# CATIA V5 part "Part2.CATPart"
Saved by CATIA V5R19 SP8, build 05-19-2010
Part number: Points_Squelette
Bounding box of the stored display mesh (mm): x 0 to 0, y -400 to 500, z -325 to 195
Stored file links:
  G:\EU_thinkMotion\CFAO_2010\MMS_groupe1\MMS_groupe1\OK\ppiault\piault\piault_cfao\Part2.CATPart
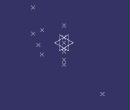
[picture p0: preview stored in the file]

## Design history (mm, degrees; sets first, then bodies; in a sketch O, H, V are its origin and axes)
Parameters
  y0 = 0 mm
  z0 = 0 mm
  y0p = -280 mm
  z0p = 0 mm
  y0s = -286 mm
  z0s = -250 mm
  y0t = 500 mm
  z0t = -300 mm
  y1 = 0 mm
  haut_axe = 195 mm
  y1p = -400 mm
  z1p = 195 mm
  y1s = 0 mm
  z1s = 62 mm
  y2 = 0 mm
  z2 = -99 mm
  y2p = 0 mm
  z2p = -64 mm
  y2s = -400 mm
  z2s = -99 mm
  y3 = 0 mm
  z3 = -190 mm
  y3p = 0 mm
  z3p = -230 mm
  y3s = -330 mm
  z3s = -190 mm
  DiametreRabatteur = 400 mm
  DiametreScie = 330 mm
  LongueurEntretoise = 130 mm
  Epaisseur = 5 mm
  bas_axe = 255 mm
  Longueur_Support = 280 mm {= DiametreRabatteur *0.7}
Set1
  Point1: (0, 0 {= y0}, 0 {= z0})
  Point2: (0, -280 {= -Longueur_Support}, 0 {= z0p})
  Point3: (0, -286 {= -0.715*DiametreRabatteur}, -275 {= -bas_axe -20mm})
  Point4: (0, 500 {= DiametreRabatteur +100mm}, -325 {= -bas_axe -70mm})
  Point5: (0, 0 {= y1}, 195 {= haut_axe})
  Point6: (0, -400 {= -DiametreRabatteur}, 195 {= haut_axe})
  Point7: (0, 0 {= y1s}, 60 {= haut_axe -Epaisseur -LongueurEntretoise})
  Point8: (0, 0 {= y2}, -100 {= -LongueurEntretoise/2 -35mm})
  Point9: (0, 0 {= y2p}, -65 {= -LongueurEntretoise /2})
  Point10: (0, -400 {= -DiametreRabatteur}, -100 {= -LongueurEntretoise/2 -35mm})
  Point11: (0, 0 {= y3}, -190 {= -bas_axe +LongueurEntretoise/2})
  Point12: (0, 0 {= y3p}, -245 {= -bas_axe+10mm})
  Point13: (0, -330 {= -DiametreScie}, -190 {= -bas_axe +LongueurEntretoise/2})
Body1 (main body)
